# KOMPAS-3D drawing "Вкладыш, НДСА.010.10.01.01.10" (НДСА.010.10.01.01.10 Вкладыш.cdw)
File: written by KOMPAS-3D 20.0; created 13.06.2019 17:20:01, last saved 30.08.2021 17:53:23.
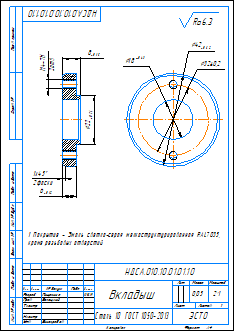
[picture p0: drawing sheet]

Sheet 1: A4, portrait

Document properties: Автор: Пользователь Windows; Параметр неуказанной шероховатости: Ra6.3; 148243450787: <item xmlns="http://appius.ru/pdm" xmlns:xs="http://www.w3.org/2001/XMLSchema" xmlns:xsi="http://www.w3.org/2001/XMLSchema-instance" xsi:type="item">  <element xmlns:d2p1="http://v8.1c.ru/8.1/data/enterprise/current-config" xsi:type="d2p1:CatalogRef.aps_Элемен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; Полное имя файла: НДСА.010.10.01.01.10 Вкладыш.m3d; 291513322430: <item xmlns="http://appius.ru/pdm" xmlns:xs="http://www.w3.org/2001/XMLSchema" xmlns:xsi="http://www.w3.org/2001/XMLSchema-instance" xsi:type="item">  <element xmlns:d2p1="http://v8.1c.ru/8.1/data/enterprise/current-config" xsi:type="d2p1:CatalogRef.aps_Элемен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; 372162023736: <item xmlns="http://appius.ru/pdm" xmlns:xs="http://www.w3.org/2001/XMLSchema" xmlns:xsi="http://www.w3.org/2001/XMLSchema-instance" xsi:type="item">  <element xmlns:d2p1="http://v8.1c.ru/8.1/data/enterprise/current-config" xsi:type="d2p1:CatalogRef.aps_Элемен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; PLM_CDWXDTO: <item xmlns="http://appius.ru/pdm" xmlns:xs="http://www.w3.org/2001/XMLSchema" xmlns:xsi="http://www.w3.org/2001/XMLSchema-instance" xsi:type="item">  <element xmlns:d2p1="http://v8.1c.ru/8.1/data/enterprise/current-config" xsi:type="d2p1:CatalogRef.aps_Элемен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; Масса: 0.0537653; 148243450887: <item xmlns="http://appius.ru/pdm" xmlns:xs="http://www.w3.org/2001/XMLSchema" xmlns:xsi="http://www.w3.org/2001/XMLSchema-instance" xsi:type="item">  <element xmlns:d2p1="http://v8.1c.ru/8.1/data/enterprise/current-config" xsi:type="d2p1:CatalogRef.aps_Элемен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

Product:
- Part/product: Вкладыш  | designation НДСА.010.10.01.01.10
    Масса: 0.0537653
    additional columns: <item xmlns="http://appius.ru/pdm" xmlns:xs="http://www.w3.org/2001/XMLSchema" x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; <item xmlns="http://appius.ru/pdm" xmlns:xs="http://www.w3.org/2001/XMLSchema" x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
    source file: НДСА.010.10.01.01.10 Вкладыш.cdw

Title block, sheet 1: Наименование: Вкладыш; designation: НДСА.010.10.01.01.10; Материал: Сталь 10  ГОСТ 1050-2013; Масса: 0,05; Количество листов документа: 1; organisation: ЭСТО; Форматы листов документа: A4; stored path: C:\Users\Конструктор 3\Desktop\PLM\НДСА.010.10.01.01.10 Вкладыш.cdw; Разработал: Пищагина; Проверил: Белецкий; Утвердил: Виноградов; Разработал, date: 13.06.19

Views: Вид 1, Местный разрез 1, Сверху, Проекционный вид 2
Referenced files in C:\Users\Конструктор 3\Desktop\PLM\: НДСА.010.10.01.01.10 Вкладыш.m3d
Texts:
  Ra6.3
  НДСА.010.10.01.01.10 Вкладыш
Dimensions and other numbers on the sheet: 22; -7Н; 4; 2отв; 1; 2фаски; 6; 8; 32±0,2; 18; 42; 2:1; 0,05; 13.06.19

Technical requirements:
  Покрытие - Эмаль светло-серая мелкоструктурированная RAL7035,
  кроме резьбовых отверстий.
